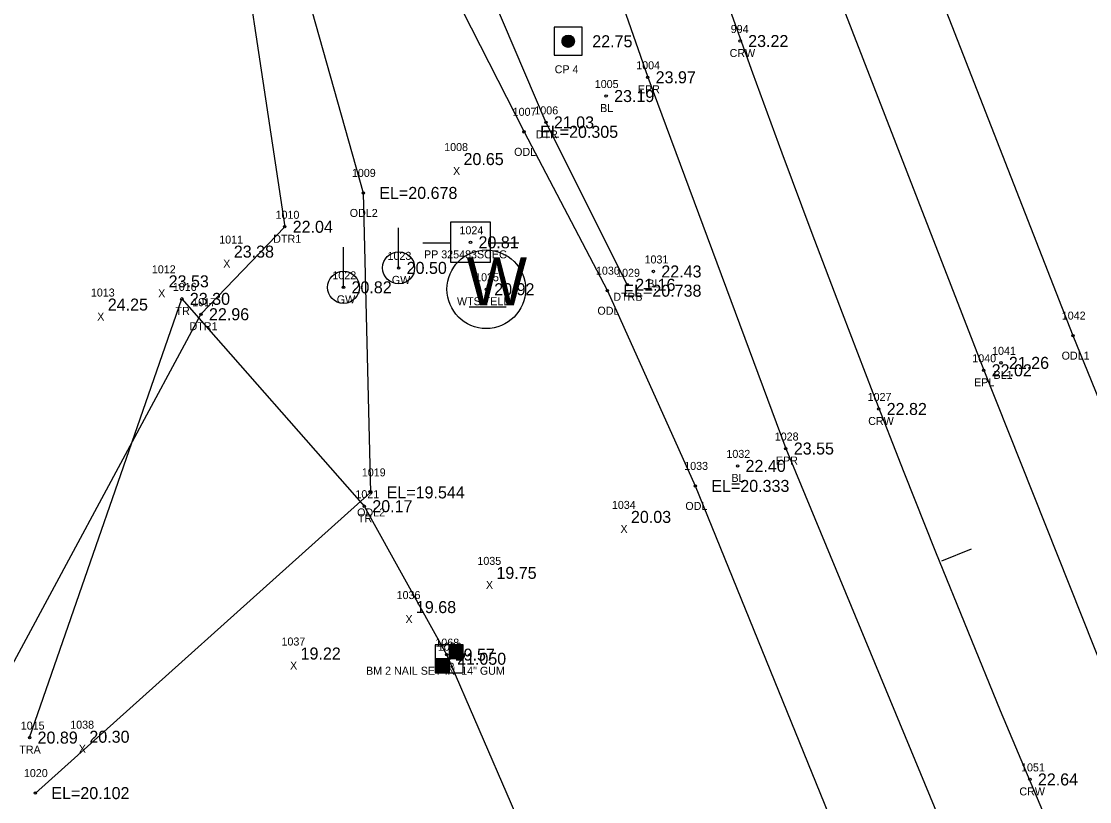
# Model space of a CAD drawing. Extents: x 2042117 to 2045853, y 303080 to 309569.
# Drawn here: x 2042863.2 to 2042996.7, y 306604.6 to 306702 of the extents above; entities that cross this region are included whole.
import ezdxf

# ---------------------------------------------------------------- set-up
doc = ezdxf.new("R2010")
doc.units = 0
for name, color, linetype in [('RD_DTM_BkLn_txCode', 7, 'Continuous'), ('RD_EX_H2O', 7, 'Continuous'), ('RD_EX_H2O_txCode', 7, 'Continuous'), ('RD_EX_Misc_txCode', 7, 'Continuous'), ('RD_EX_Road', 7, 'Continuous'), ('RD_EX_Road_txCode', 7, 'Continuous'), ('RD_EX_TX_H2O_ELEV', 7, 'Continuous'), ('RD_EX_TX_Misc_ELEV', 7, 'Continuous'), ('RD_EX_TX_Road_ELEV', 7, 'Continuous'), ('RD_EX_TX_UT_ELEV', 7, 'Continuous'), ('RD_EX_TX_VEG_ELEV', 7, 'Continuous'), ('RD_EX_UT', 7, 'Continuous'), ('RD_EX_UT_txCode', 7, 'Continuous'), ('RD_EX_VEG', 7, 'Continuous'), ('RD_EX_VEG_txCode', 7, 'Continuous'), ('RD_HC_Cl', 7, 'Continuous'), ('RD_HC_Data_Tic', 7, 'Continuous'), ('RD_HC_Survey', 7, 'Continuous'), ('RD_HC_Survey_ELEV', 7, 'Continuous'), ('RD_HC_Survey_txCode', 7, 'Continuous'), ('RD_SMD_Locator', 7, 'Continuous')]:
    doc.layers.add(name, color=color, linetype=linetype)

msp = doc.modelspace()

# ---------------------------------------------------------------- linework, layer by layer
at = {"layer": 'RD_EX_H2O'}
for points in [[(2042865.43, 307427.05), (2042866.84, 307378.87), (2042866.82, 307329.93), (2042876.23, 307282.16), (2042878.43, 307232.86), (2042875.08, 307184.77), (2042887.19, 307136.65), (2042884.32, 307120.02), (2042882.74, 307087.49), (2042892.51, 307039.16), (2042896.41, 306990.42), (2042899.37, 306973.37), (2042910.05, 306942.23), (2042920.75, 306896.67), (2042927.15, 306846.78), (2042945.6, 306801.59), (2042960.32, 306754.61), (2042976.65, 306708.74), (2042994.63, 306662.76), (2043013.3, 306616.98), (2043029.17, 306571.91), (2043050.77, 306528.53)], [(2042809.74, 307126.16), (2042806.56, 307122.63), (2042790.31, 307116.78), (2042788.49, 307114.78), (2042791.89, 307113.57), (2042804.81, 307114.94), (2042810.25, 307075.93), (2042820.25, 307025.92), (2042830.4, 306977.21), (2042843.29, 306928.12), (2042852.91, 306878.24), (2042864.55, 306828.43), (2042879.23, 306781.72), (2042889.45, 306748.73), (2042886.16, 306741.98), (2042888.34, 306727.94), (2042896.13, 306676.35), (2042885.67, 306665.43), (2042857.25, 306612.72)], [(2042809.74, 307126.16), (2042815.01, 307124.31), (2042821.79, 307118.99), (2042825.8, 307110.2), (2042827.88, 307100.21), (2042830.08, 307078.71), (2042836.25, 307029.11), (2042845.48, 306980.04), (2042852.07, 306929.46), (2042864.58, 306881.26), (2042879.31, 306833.06), (2042893.37, 306784.78), (2042908.76, 306736.23), (2042928.77, 306689.39), (2042938.94, 306669.11)], [(2042812.2, 307117.75), (2042817.66, 307076.99), (2042828.97, 307027.39), (2042840.42, 306978.95), (2042848.44, 306929.66), (2042859.84, 306880.36), (2042873.68, 306831.67), (2042888.54, 306783.43), (2042900.59, 306749.27), (2042902.9, 306733.67), (2042926.04, 306688.21), (2042936.45, 306668.37), (2042947.44, 306643.99), (2042966.18, 306597.91), (2042985.34, 306551.14), (2042987.61, 306538.59)], [(2042810.02, 307117.36), (2042813.87, 307076.18), (2042825.65, 307027), (2042835.99, 306978.45), (2042846.19, 306929.27), (2042857.5, 306879.97), (2042870.3, 306830.67), (2042885.37, 306782.68), (2042895.57, 306748.28), (2042892.03, 306740.63), (2042891.66, 306731.27), (2042905.95, 306680.58), (2042906.87, 306643.18), (2042864.97, 306605.63)]]:
    msp.add_lwpolyline(points, dxfattribs=at)
at = {"layer": 'RD_EX_Road'}
for points in [[(2042921.09, 306844.85), (2042934.41, 306798.2), (2042949.37, 306750.96), (2042965.62, 306704.44), (2042983.48, 306658.43), (2043001.91, 306612.18), (2043021.64, 306567.98), (2043042.58, 306523.81), (2043065.05, 306479.23), (2043088.14, 306436.09), (2043112.53, 306392.81), (2043137.38, 306350.66), (2043162.88, 306309.77)], [(2042895.94, 306837.56), (2042909.76, 306789.89), (2042925.08, 306742.02), (2042941.49, 306695.02), (2042958.75, 306648.66), (2042978.01, 306602.25), (2042998.08, 306556.93), (2043019.38, 306511.63), (2043041.84, 306466.86), (2043065.03, 306422.83), (2043089.72, 306379.65), (2043115.12, 306336.87), (2043141.61, 306295.02)]]:
    msp.add_lwpolyline(points, dxfattribs=at)
at = {"layer": 'RD_EX_UT'}
for p, q in [((2042910.37, 306671.22), (2042910.37, 306676.22)), ((2042921.84, 306676.92), (2042916.84, 306676.92)), ((2042916.84, 306676.92), (2042916.84, 306671.92)), ((2042921.84, 306671.92), (2042921.84, 306676.92)), ((2042903.48, 306668.79), (2042903.48, 306673.79)), ((2042913.41, 306674.35), (2042916.88, 306674.35)), ((2042921.77, 306674.35), (2042925.41, 306674.35)), ((2042916.84, 306671.92), (2042921.84, 306671.92)), ((2042919.19, 306666.34), (2042923.82, 306666.34))]:
    msp.add_line(p, q, dxfattribs=at)
for centre, radius in [((2042910.37, 306671.22), 2), ((2042921.32, 306668.55), 4.91), ((2042903.48, 306668.79), 2)]:
    msp.add_circle(centre, radius, dxfattribs=at)
at = {"layer": 'RD_EX_VEG'}
msp.add_lwpolyline([(2042864.25, 306612.56), (2042883.28, 306667.35), (2042906.08, 306641.46), (2042916.37, 306622.92), (2042928.46, 306594.97), (2042955.8, 306539.7), (2042967.97, 306505.97)], dxfattribs=at)
at = {"layer": 'RD_HC_Cl'}
msp.add_arc((2044751.25, 307348.43), 1911.29, 137.68184, 219.86836, dxfattribs=at)
at = {"layer": 'RD_HC_Data_Tic'}
msp.add_line((2042978.25, 306634.62), (2042981.96, 306636.12), dxfattribs=at)
at = {"layer": 'RD_HC_Survey'}
for p, q in [((2042930.87, 306699.2), (2042930.87, 306699.84)), ((2042930.9, 306699.15), (2042930.9, 306699.89)), ((2042930.92, 306699.11), (2042930.92, 306699.93)), ((2042930.95, 306699.07), (2042930.95, 306699.97)), ((2042930.97, 306699.04), (2042930.97, 306700)), ((2042931, 306699.01), (2042931, 306700.03)), ((2042931.02, 306698.98), (2042931.02, 306700.06)), ((2042931.05, 306698.96), (2042931.05, 306700.08)), ((2042931.07, 306698.94), (2042931.07, 306700.1)), ((2042931.1, 306698.92), (2042931.1, 306700.12)), ((2042931.12, 306698.9), (2042931.12, 306700.14)), ((2042931.15, 306698.88), (2042931.15, 306700.16)), ((2042931.17, 306698.86), (2042931.17, 306700.18)), ((2042931.2, 306698.85), (2042931.2, 306700.19)), ((2042931.22, 306698.84), (2042931.22, 306700.2)), ((2042931.25, 306698.82), (2042931.25, 306700.22)), ((2042931.27, 306698.81), (2042931.27, 306700.23)), ((2042931.29, 306698.8), (2042931.29, 306700.24)), ((2042931.32, 306698.79), (2042931.32, 306700.25)), ((2042931.34, 306698.79), (2042931.34, 306700.25)), ((2042931.37, 306698.78), (2042931.37, 306700.26)), ((2042931.39, 306698.77), (2042931.39, 306700.27)), ((2042931.42, 306698.77), (2042931.42, 306700.27)), ((2042931.44, 306698.76), (2042931.44, 306700.28)), ((2042931.47, 306698.76), (2042931.47, 306700.28)), ((2042931.49, 306698.75), (2042931.49, 306700.29)), ((2042931.52, 306698.75), (2042931.52, 306700.29)), ((2042931.54, 306698.75), (2042931.54, 306700.29)), ((2042931.57, 306698.75), (2042931.57, 306700.29)), ((2042931.59, 306698.75), (2042931.59, 306700.29)), ((2042931.62, 306698.75), (2042931.62, 306700.29)), ((2042931.64, 306698.75), (2042931.64, 306700.29)), ((2042931.67, 306698.76), (2042931.67, 306700.28)), ((2042931.69, 306698.76), (2042931.69, 306700.28)), ((2042931.72, 306698.76), (2042931.72, 306700.28)), ((2042931.74, 306698.77), (2042931.74, 306700.27)), ((2042931.77, 306698.78), (2042931.77, 306700.27)), ((2042931.79, 306698.78), (2042931.79, 306700.26)), ((2042931.81, 306698.79), (2042931.81, 306700.25)), ((2042931.84, 306698.8), (2042931.84, 306700.24)), ((2042931.86, 306698.81), (2042931.86, 306700.23)), ((2042931.89, 306698.82), (2042931.89, 306700.22)), ((2042931.91, 306698.83), (2042931.91, 306700.21)), ((2042931.94, 306698.84), (2042931.94, 306700.2)), ((2042931.96, 306698.86), (2042931.96, 306700.18)), ((2042931.99, 306698.87), (2042931.99, 306700.17)), ((2042932.01, 306698.89), (2042932.01, 306700.15)), ((2042932.04, 306698.91), (2042932.04, 306700.13)), ((2042932.06, 306698.93), (2042932.06, 306700.11)), ((2042932.09, 306698.95), (2042932.09, 306700.09)), ((2042932.11, 306698.97), (2042932.11, 306700.07)), ((2042932.14, 306699), (2042932.14, 306700.04)), ((2042932.16, 306699.02), (2042932.16, 306700.02)), ((2042932.19, 306699.05), (2042932.19, 306699.99)), ((2042932.21, 306699.09), (2042932.21, 306699.95)), ((2042932.24, 306699.13), (2042932.24, 306699.91)), ((2042932.26, 306699.17), (2042932.26, 306699.87)), ((2042930.82, 306699.34), (2042930.82, 306699.7)), ((2042930.85, 306699.26), (2042930.85, 306699.78)), ((2042932.28, 306699.23), (2042932.28, 306699.81)), ((2042932.31, 306699.3), (2042932.31, 306699.74)), ((2042932.33, 306699.41), (2042932.33, 306699.63)), ((2042916.67, 306624.16), (2042916.67, 306620.66)), ((2042916.69, 306624.16), (2042916.69, 306622.41)), ((2042916.71, 306624.16), (2042916.71, 306622.41)), ((2042916.74, 306624.16), (2042916.74, 306622.41)), ((2042916.76, 306624.16), (2042916.76, 306622.41)), ((2042916.79, 306624.16), (2042916.79, 306622.41)), ((2042916.81, 306624.16), (2042916.81, 306622.41)), ((2042916.84, 306624.16), (2042916.84, 306622.41)), ((2042916.86, 306624.16), (2042916.86, 306622.41)), ((2042916.89, 306624.16), (2042916.89, 306622.41)), ((2042916.91, 306624.16), (2042916.91, 306622.41)), ((2042916.94, 306624.16), (2042916.94, 306622.41)), ((2042916.96, 306624.16), (2042916.96, 306622.41)), ((2042916.99, 306624.16), (2042916.99, 306622.41)), ((2042917.01, 306624.16), (2042917.01, 306622.41)), ((2042917.03, 306624.16), (2042917.03, 306622.41)), ((2042917.06, 306624.16), (2042917.06, 306622.41)), ((2042917.08, 306624.16), (2042917.08, 306622.41)), ((2042917.11, 306624.16), (2042917.11, 306622.41)), ((2042917.13, 306624.16), (2042917.13, 306622.41)), ((2042917.16, 306624.16), (2042917.16, 306622.41)), ((2042917.18, 306624.16), (2042917.18, 306622.41)), ((2042917.21, 306624.16), (2042917.21, 306622.41)), ((2042917.23, 306624.16), (2042917.23, 306622.41)), ((2042917.26, 306624.16), (2042917.26, 306622.41)), ((2042917.28, 306624.16), (2042917.28, 306622.41)), ((2042917.31, 306624.16), (2042917.31, 306622.41)), ((2042917.33, 306624.16), (2042917.33, 306622.41)), ((2042917.36, 306624.16), (2042917.36, 306622.41)), ((2042917.38, 306624.16), (2042917.38, 306622.41)), ((2042917.41, 306624.16), (2042917.41, 306622.41)), ((2042917.43, 306624.16), (2042917.43, 306622.41)), ((2042917.46, 306624.16), (2042917.46, 306622.41)), ((2042917.48, 306624.16), (2042917.48, 306622.41)), ((2042917.5, 306624.16), (2042917.5, 306622.41)), ((2042917.53, 306624.16), (2042917.53, 306622.41)), ((2042917.55, 306624.16), (2042917.55, 306622.41)), ((2042917.58, 306624.16), (2042917.58, 306622.41)), ((2042917.6, 306624.16), (2042917.6, 306622.41)), ((2042917.63, 306624.16), (2042917.63, 306622.41)), ((2042917.65, 306624.16), (2042917.65, 306622.41)), ((2042917.68, 306624.16), (2042917.68, 306622.41)), ((2042917.7, 306624.16), (2042917.7, 306622.41)), ((2042917.73, 306624.16), (2042917.73, 306622.41)), ((2042917.75, 306624.16), (2042917.75, 306622.41)), ((2042917.78, 306624.16), (2042917.78, 306622.41)), ((2042917.8, 306624.16), (2042917.8, 306622.41)), ((2042917.83, 306624.16), (2042917.83, 306622.41)), ((2042917.85, 306624.16), (2042917.85, 306622.41)), ((2042917.88, 306624.16), (2042917.88, 306622.41)), ((2042917.9, 306624.16), (2042917.9, 306622.41)), ((2042917.93, 306624.16), (2042917.93, 306622.41)), ((2042917.95, 306624.16), (2042917.95, 306622.41)), ((2042917.98, 306624.16), (2042917.98, 306622.41)), ((2042918, 306624.16), (2042918, 306622.41)), ((2042918.02, 306624.16), (2042918.02, 306622.41)), ((2042918.05, 306624.16), (2042918.05, 306622.41)), ((2042918.07, 306624.16), (2042918.07, 306622.41)), ((2042918.1, 306624.16), (2042918.1, 306622.41)), ((2042918.12, 306624.16), (2042918.12, 306622.41)), ((2042918.15, 306624.16), (2042918.15, 306622.41)), ((2042918.17, 306624.16), (2042918.17, 306622.41)), ((2042918.2, 306624.16), (2042918.2, 306622.41)), ((2042918.22, 306624.16), (2042918.22, 306622.41)), ((2042918.25, 306624.16), (2042918.25, 306622.41)), ((2042918.27, 306624.16), (2042918.27, 306622.41)), ((2042918.3, 306624.16), (2042918.3, 306622.41)), ((2042918.32, 306624.16), (2042918.32, 306622.41)), ((2042918.35, 306624.16), (2042918.35, 306622.41)), ((2042918.37, 306624.16), (2042918.37, 306622.41)), ((2042918.4, 306624.16), (2042918.4, 306622.41)), ((2042918.42, 306622.41), (2042914.92, 306622.41)), ((2042914.92, 306622.41), (2042914.92, 306620.66)), ((2042914.95, 306622.41), (2042914.95, 306620.66)), ((2042914.97, 306622.41), (2042914.97, 306620.66)), ((2042914.99, 306622.41), (2042914.99, 306620.66)), ((2042915.02, 306622.41), (2042915.02, 306620.66)), ((2042915.04, 306622.41), (2042915.04, 306620.66)), ((2042915.07, 306622.41), (2042915.07, 306620.66)), ((2042915.09, 306622.41), (2042915.09, 306620.66)), ((2042915.12, 306622.41), (2042915.12, 306620.66)), ((2042915.14, 306622.41), (2042915.14, 306620.66)), ((2042915.17, 306622.41), (2042915.17, 306620.66)), ((2042915.19, 306622.41), (2042915.19, 306620.66)), ((2042915.22, 306622.41), (2042915.22, 306620.66)), ((2042915.24, 306622.41), (2042915.24, 306620.66)), ((2042915.27, 306622.41), (2042915.27, 306620.66)), ((2042915.29, 306622.41), (2042915.29, 306620.66)), ((2042915.32, 306622.41), (2042915.32, 306620.66)), ((2042915.34, 306622.41), (2042915.34, 306620.66)), ((2042915.37, 306622.41), (2042915.37, 306620.66)), ((2042915.39, 306622.41), (2042915.39, 306620.66)), ((2042915.42, 306622.41), (2042915.42, 306620.66)), ((2042915.44, 306622.41), (2042915.44, 306620.66)), ((2042915.47, 306622.41), (2042915.47, 306620.66)), ((2042915.49, 306622.41), (2042915.49, 306620.66)), ((2042915.51, 306622.41), (2042915.51, 306620.66)), ((2042915.54, 306622.41), (2042915.54, 306620.66)), ((2042915.56, 306622.41), (2042915.56, 306620.66)), ((2042915.59, 306622.41), (2042915.59, 306620.66)), ((2042915.61, 306622.41), (2042915.61, 306620.66)), ((2042915.64, 306622.41), (2042915.64, 306620.66)), ((2042915.66, 306622.41), (2042915.66, 306620.66)), ((2042915.69, 306622.41), (2042915.69, 306620.66)), ((2042915.71, 306622.41), (2042915.71, 306620.66)), ((2042915.74, 306622.41), (2042915.74, 306620.66)), ((2042915.76, 306622.41), (2042915.76, 306620.66)), ((2042915.79, 306622.41), (2042915.79, 306620.66)), ((2042915.81, 306622.41), (2042915.81, 306620.66)), ((2042915.84, 306622.41), (2042915.84, 306620.66)), ((2042915.86, 306622.41), (2042915.86, 306620.66)), ((2042915.89, 306622.41), (2042915.89, 306620.66)), ((2042915.91, 306622.41), (2042915.91, 306620.66)), ((2042915.94, 306622.41), (2042915.94, 306620.66)), ((2042915.96, 306622.41), (2042915.96, 306620.66)), ((2042915.98, 306622.41), (2042915.98, 306620.66)), ((2042916.01, 306622.41), (2042916.01, 306620.66)), ((2042916.03, 306622.41), (2042916.03, 306620.66)), ((2042916.06, 306622.41), (2042916.06, 306620.66)), ((2042916.08, 306622.41), (2042916.08, 306620.66)), ((2042916.11, 306622.41), (2042916.11, 306620.66)), ((2042916.13, 306622.41), (2042916.13, 306620.66)), ((2042916.16, 306622.41), (2042916.16, 306620.66)), ((2042916.18, 306622.41), (2042916.18, 306620.66)), ((2042916.21, 306622.41), (2042916.21, 306620.66)), ((2042916.23, 306622.41), (2042916.23, 306620.66)), ((2042916.26, 306622.41), (2042916.26, 306620.66)), ((2042916.28, 306622.41), (2042916.28, 306620.66)), ((2042916.31, 306622.41), (2042916.31, 306620.66)), ((2042916.33, 306622.41), (2042916.33, 306620.66)), ((2042916.36, 306622.41), (2042916.36, 306620.66)), ((2042916.38, 306622.41), (2042916.38, 306620.66)), ((2042916.41, 306622.41), (2042916.41, 306620.66)), ((2042916.43, 306622.41), (2042916.43, 306620.66)), ((2042916.46, 306622.41), (2042916.46, 306620.66)), ((2042916.48, 306622.41), (2042916.48, 306620.66)), ((2042916.5, 306622.41), (2042916.5, 306620.66)), ((2042916.53, 306622.41), (2042916.53, 306620.66)), ((2042916.55, 306622.41), (2042916.55, 306620.66)), ((2042916.58, 306622.41), (2042916.58, 306620.66)), ((2042916.6, 306622.41), (2042916.6, 306620.66)), ((2042916.63, 306622.41), (2042916.63, 306620.66)), ((2042916.65, 306622.41), (2042916.65, 306620.66))]:
    msp.add_line(p, q, dxfattribs=at)
for points in [[(2042933.32, 306701.27), (2042929.82, 306701.27), (2042929.82, 306697.77), (2042933.32, 306697.77)], [(2042918.42, 306624.16), (2042914.92, 306624.16), (2042914.92, 306620.66), (2042918.42, 306620.66)]]:
    msp.add_lwpolyline(points, close=True, dxfattribs=at)
msp.add_circle((2042931.57, 306699.52), 0.769, dxfattribs=at)
at = {"layer": 'RD_SMD_Locator'}
for centre in [(2042931.57, 306699.52), (2042953.05, 306699.55), (2042941.49, 306695.02), (2042936.3, 306692.68), (2042928.77, 306689.39), (2042926.04, 306688.21), (2042905.95, 306680.58), (2042896.13, 306676.35), (2042919.35, 306674.41), (2042910.37, 306671.22), (2042942.2, 306670.77), (2042938.94, 306669.11), (2042903.48, 306668.79), (2042921.32, 306668.55), (2042936.45, 306668.37), (2042883.28, 306667.35), (2042885.67, 306665.43), (2042994.63, 306662.76), (2042983.48, 306658.43), (2042985.63, 306659.36), (2042970.36, 306653.6), (2042958.75, 306648.66), (2042952.72, 306646.49), (2042947.44, 306643.99), (2042906.87, 306643.18), (2042906.08, 306641.46), (2042916.37, 306622.92), (2042916.67, 306622.41), (2042864.25, 306612.56), (2042989.25, 306607.34), (2042864.97, 306605.63)]:
    msp.add_circle(centre, 0.15, dxfattribs=at)

# ---------------------------------------------------------------- texts
at = {"layer": 'RD_DTM_BkLn_txCode'}
for s, p in [('1005', (2042934.88, 306693.68)), ('BL', (2042935.55, 306690.68)), ('1031', (2042941.1, 306671.77)), ('BL', (2042941.44, 306668.77)), ('1041', (2042984.53, 306660.36)), ('BL1', (2042984.71, 306657.36)), ('1032', (2042951.33, 306647.49)), ('BL', (2042951.96, 306644.49))]:
    msp.add_text(s, height=1, dxfattribs=at).set_placement(p)
at = {"layer": 'RD_EX_H2O_txCode'}
for s, p in [('1007', (2042924.62, 306690.21)), ('1006', (2042927.33, 306690.39)), ('DTR', (2042927.51, 306687.39)), ('ODL', (2042924.8, 306685.21)), ('1009', (2042904.53, 306682.58)), ('ODL2', (2042904.26, 306677.58)), ('1010', (2042894.99, 306677.35)), ('DTR1', (2042894.7, 306674.35)), ('1030', (2042935.03, 306670.37)), ('1029', (2042937.55, 306670.11)), ('DTRB', (2042937.2, 306667.11)), ('1017', (2042884.57, 306666.43)), ('ODL', (2042935.21, 306665.37)), ('1042', (2042993.24, 306664.76)), ('DTR1', (2042884.24, 306663.43)), ('ODL1', (2042993.22, 306659.76)), ('1033', (2042946.06, 306645.99)), ('1019', (2042905.77, 306645.18)), ('ODL2', (2042905.18, 306640.18)), ('ODL', (2042946.2, 306640.99)), ('1020', (2042863.54, 306607.63))]:
    msp.add_text(s, height=1, dxfattribs=at).set_placement(p)
at = {"layer": 'RD_EX_Misc_txCode'}
for s, p in [('1008', (2042916.06, 306685.81)), ('X', (2042917.17, 306682.81)), ('1011', (2042887.95, 306674.25)), ('X', (2042888.45, 306671.25)), ('1012', (2042879.53, 306670.54)), ('1013', (2042871.91, 306667.64)), ('X', (2042880.32, 306667.54)), ('X', (2042872.7, 306664.64)), ('1034', (2042937.02, 306641.12)), ('X', (2042938.09, 306638.12)), ('1035', (2042920.21, 306634.13)), ('X', (2042921.28, 306631.13)), ('1036', (2042910.12, 306629.86)), ('X', (2042911.22, 306626.86)), ('1037', (2042895.73, 306624.06)), ('X', (2042896.8, 306621.06)), ('1038', (2042869.33, 306613.67)), ('X', (2042870.4, 306610.67))]:
    msp.add_text(s, height=1, dxfattribs=at).set_placement(p)
at = {"layer": 'RD_EX_Road_txCode'}
for s, p in [('1004', (2042940.06, 306696.02)), ('EPR', (2042940.26, 306693.02)), ('1040', (2042982.06, 306659.43)), ('EPL', (2042982.28, 306656.43)), ('1028', (2042957.37, 306649.66)), ('EPR', (2042957.52, 306646.66))]:
    msp.add_text(s, height=1, dxfattribs=at).set_placement(p)
at = {"layer": 'RD_EX_TX_H2O_ELEV'}
for s, p in [('21.03', (2042929.77, 306688.64)), ('EL=20.305', (2042928.04, 306687.46)), ('EL=20.678', (2042907.95, 306679.83)), ('22.04', (2042897.13, 306675.6)), ('EL=20.738', (2042938.45, 306667.62)), ('21.16', (2042939.94, 306668.36)), ('22.96', (2042886.67, 306664.68)), ('EL=19.544', (2042908.87, 306642.43)), ('EL=20.333', (2042949.44, 306643.24)), ('EL=20.102', (2042866.97, 306604.88))]:
    msp.add_text(s, height=1.5, dxfattribs=at).set_placement(p)
at = {"layer": 'RD_EX_TX_Misc_ELEV'}
for s, p in [('23.19', (2042937.3, 306691.93)), ('20.65', (2042918.48, 306684.06)), ('23.38', (2042889.77, 306672.5)), ('22.43', (2042943.2, 306670.02)), ('23.53', (2042881.63, 306668.79)), ('24.25', (2042874.02, 306665.89)), ('21.26', (2042986.63, 306658.61)), ('22.40', (2042953.72, 306645.74)), ('20.03', (2042939.4, 306639.37)), ('19.75', (2042922.59, 306632.38)), ('19.68', (2042912.53, 306628.11)), ('19.22', (2042898.12, 306622.31)), ('20.30', (2042871.72, 306611.92))]:
    msp.add_text(s, height=1.5, dxfattribs=at).set_placement(p)
at = {"layer": 'RD_EX_TX_Road_ELEV'}
for s, p in [('23.97', (2042942.49, 306694.27)), ('22.02', (2042984.48, 306657.68)), ('23.55', (2042959.75, 306647.91))]:
    msp.add_text(s, height=1.5, dxfattribs=at).set_placement(p)
at = {"layer": 'RD_EX_TX_UT_ELEV'}
for s, p in [('20.50', (2042911.37, 306670.47)), ('20.82', (2042904.48, 306668.04)), ('20.92', (2042922.32, 306667.8))]:
    msp.add_text(s, height=1.5, dxfattribs=at).set_placement(p)
at = {"layer": 'RD_EX_TX_VEG_ELEV'}
for s, p in [('23.30', (2042884.28, 306666.6)), ('20.17', (2042907.08, 306640.71)), ('19.57', (2042917.37, 306622.17)), ('20.89', (2042865.25, 306611.81))]:
    msp.add_text(s, height=1.5, dxfattribs=at).set_placement(p)
at = {"layer": 'RD_EX_UT'}
msp.add_text('W', height=6, dxfattribs=at).set_placement((2042918.85, 306666.54))
at = {"layer": 'RD_EX_UT_txCode'}
for s, p in [('1024', (2042917.97, 306675.41)), ('1023', (2042908.98, 306672.22)), ('PP 325483SCEG', (2042913.54, 306672.41)), ('1022', (2042902.09, 306669.79)), ('1025', (2042919.93, 306669.55)), ('GW', (2042909.52, 306669.22)), ('GW', (2042902.64, 306666.79)), ('WTS TELE', (2042917.66, 306666.55))]:
    msp.add_text(s, height=1, dxfattribs=at).set_placement(p)
at = {"layer": 'RD_EX_VEG_txCode'}
for s, p in [('1016', (2042882.15, 306668.35)), ('TR', (2042882.48, 306665.35)), ('1021', (2042904.97, 306642.46)), ('TR', (2042905.28, 306639.46)), ('1068', (2042914.96, 306623.92)), ('TR', (2042915.58, 306620.92)), ('1015', (2042863.15, 306613.56)), ('TRA', (2042862.97, 306610.56))]:
    msp.add_text(s, height=1, dxfattribs=at).set_placement(p)
at = {"layer": 'RD_HC_Survey_ELEV'}
for s, p in [('22.75', (2042934.57, 306698.77)), ('23.22', (2042954.05, 306698.8)), ('20.81', (2042920.35, 306673.66)), ('22.82', (2042971.36, 306652.85)), ('21.050', (2042917.67, 306621.66)), ('22.64', (2042990.25, 306606.59))]:
    msp.add_text(s, height=1.5, dxfattribs=at).set_placement(p)
at = {"layer": 'RD_HC_Survey_txCode'}
for s, p in [('994', (2042951.87, 306700.55)), ('CRW', (2042951.73, 306697.55)), ('CP 4', (2042929.87, 306695.52)), ('1027', (2042968.98, 306654.6)), ('CRW', (2042969.05, 306651.6)), ('1026', (2042915.26, 306623.41)), ('BM 2 NAIL SET IN  14" GUM', (2042906.3, 306620.41)), ('1051', (2042988.15, 306608.34)), ('CRW', (2042987.94, 306605.34))]:
    msp.add_text(s, height=1, dxfattribs=at).set_placement(p)

doc.saveas('drawing.dxf')
